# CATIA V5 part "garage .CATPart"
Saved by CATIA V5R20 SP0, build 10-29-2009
Part number: garage 
Bounding box of the stored display mesh (mm): x -10 to 0, y 0 to 710, z 0 to 350
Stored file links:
  C:\Users\bensf\Desktop\bouthaina\garage .CATPart
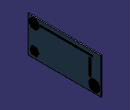
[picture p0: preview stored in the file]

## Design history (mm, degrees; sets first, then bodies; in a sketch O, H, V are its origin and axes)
Body1 (main body)
  Sketch1 on yz-plane, origin (0, 0, 0), H (0, 1, 0), V (0, 0, 1)
    line L1 (0, 0) -> (710, 0)
    line L2 (710, 0) -> (710, 350)
    line L3 (710, 350) -> (0, 350)
    line L4 (0, 350) -> (0, 0)
    length L1 = 710
    length L4 = 350
    horizontal: L1 H, L3 H
    vertical: L2 V, L4 V
  Pad1: profile Sketch1, direction (-1, 0, 0), length 10
  Sketch2 on start face of Pad1, origin (0, 0, 0), H (0, 1, 0), V (0, 0, 1)
    circle A1 centre (58.4325, 292.4086) radius 48.4713
    circle A2 centre (645.1385, 64.4153) radius 54.4315
    line L1 (631.2975, 311.6648) -> (113.7966, 311.6648)
    line L2 (113.7966, 311.6648) -> (113.7966, 297.0301)
    line L3 (113.7966, 297.0301) -> (631.2975, 297.0301)
    line L4 (631.2975, 297.0301) -> (631.2975, 311.6648)
    line L5 (590.5433, 282.3954) -> (614.3807, 282.3954)
    line L6 (614.3807, 282.3954) -> (614.3807, 119.8731)
    line L7 (614.3807, 119.8731) -> (590.5433, 119.8731)
    line L8 (590.5433, 119.8731) -> (590.5433, 282.3954)
    point P11 (62.5381, 63.645)
    point P12 (86.1436, 26.3955)
    point P13 (106.5999, 65.4632)
    point P14 (82.9944, 102.7128)
    point P15 (38.9325, 100.8946)
    point P16 (18.4762, 61.8268)
    point P17 (42.0817, 24.5773)
    point P18 (96.3717, 45.9293)
    line L9 (86.1436, 26.3955) -> (106.5999, 65.4632)
    line L10 (106.5999, 65.4632) -> (82.9944, 102.7128)
    line L11 (82.9944, 102.7128) -> (38.9325, 100.8946)
    line L12 (38.9325, 100.8946) -> (18.4762, 61.8268)
    line L13 (18.4762, 61.8268) -> (42.0817, 24.5773)
    line L14 (42.0817, 24.5773) -> (86.1436, 26.3955)
    construction line L15 (62.5381, 63.645) -> (96.3717, 45.9293)
    construction circle A3 centre (62.5381, 63.645) radius 44.0993
    construction arc A4 centre (18.4762, 61.8268) radius 44.0993 from (38.9325, 100.8946) to (42.0817, 24.5773) cw
    construction arc A5 centre (106.5999, 65.4632) radius 44.0993 from (82.9944, 102.7128) to (86.1436, 26.3955) ccw
    horizontal: L1 H, L3 H, L5 H, L7 H
    vertical: L2 V, L4 V, L6 V, L8 V
    coincidence: A3 P12, A3 P13, A3 P14, A3 P15, A3 P16, A3 P17, A4 P11, A5 P11
    midpoint: P18 L9
    parallelism: L9 L12
  Pocket1: profile Sketch2, direction (-1, 0, 0), length 5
